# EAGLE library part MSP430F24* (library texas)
MIXED SIGNAL MICROCONTROLLER Source: http://focus.ti.com/lit/ds/symlink/msp430f2471.pdf
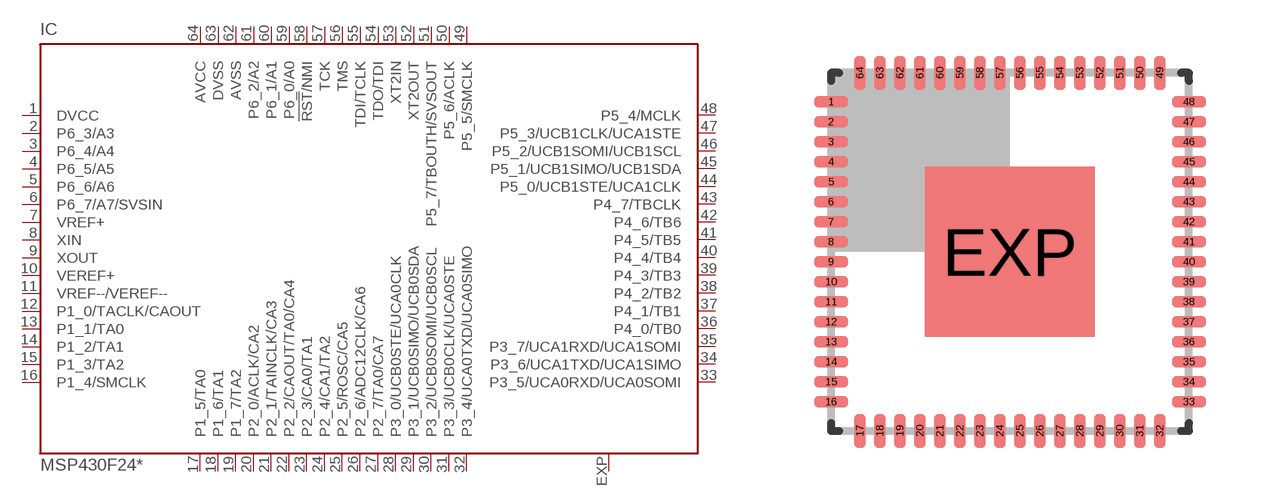
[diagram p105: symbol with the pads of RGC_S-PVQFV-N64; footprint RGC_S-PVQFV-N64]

Designator prefix IC

## MSP430F2410TRGC (MPN: MSP430F2410TRGCT; OC_FARNELL: 1649436; OC_NEWARK: 65M1704), MSP430F2447TRGC (OC_FARNELL: unknown; OC_NEWARK: unknown), MSP430F2448TRGC (OC_FARNELL: unknown; OC_NEWARK: unknown), MSP430F2449TRGC (OC_FARNELL: unknown; OC_NEWARK: unknown)  [RGC_S-PVQFV-N64]
1  DVCC  pwr
2  P6_3/A3
3  P6_4/A4
4  P6_5/A5
5  P6_6/A6
6  P6_7/A7/SVSIN
7  VREF+  out
8  XIN  in
9  XOUT  out
10  VEREF+  in
11  VREF--/VEREF--  in
12  P1_0/TACLK/CAOUT
13  P1_1/TA0
14  P1_2/TA1
15  P1_3/TA2
16  P1_4/SMCLK
17  P1_5/TA0
18  P1_6/TA1
19  P1_7/TA2
20  P2_0/ACLK/CA2
21  P2_1/TAINCLK/CA3
22  P2_2/CAOUT/TA0/CA4
23  P2_3/CA0/TA1
24  P2_4/CA1/TA2
25  P2_5/ROSC/CA5
26  P2_6/ADC12CLK/CA6
27  P2_7/TA0/CA7
28  P3_0/UCB0STE/UCA0CLK
29  P3_1/UCB0SIMO/UCB0SDA
30  P3_2/UCB0SOMI/UCB0SCL
31  P3_3/UCB0CLK/UCA0STE
32  P3_4/UCA0TXD/UCA0SIMO
33  P3_5/UCA0RXD/UCA0SOMI
34  P3_6/UCA1TXD/UCA1SIMO
35  P3_7/UCA1RXD/UCA1SOMI
36  P4_0/TB0
37  P4_1/TB1
38  P4_2/TB2
39  P4_3/TB3
40  P4_4/TB4
41  P4_5/TB5
42  P4_6/TB6
43  P4_7/TBCLK
44  P5_0/UCB1STE/UCA1CLK
45  P5_1/UCB1SIMO/UCB1SDA
46  P5_2/UCB1SOMI/UCB1SCL
47  P5_3/UCB1CLK/UCA1STE
48  P5_4/MCLK
49  P5_5/SMCLK
50  P5_6/ACLK
51  P5_7/TBOUTH/SVSOUT
52  XT2OUT  out
53  XT2IN  in
54  TDO/TDI
55  TDI/TCLK  in
56  TMS  in
57  TCK  in
58  !RST!/NMI  in
59  P6_0/A0
60  P6_1/A1
61  P6_2/A2
62  AVSS  pwr
63  DVSS  pwr
64  AVCC  pwr
EXP  EXP  pas

## Footprint RGC_S-PVQFV-N64 (pad centres in mm)
RGC(S-PVQFN-N64) CUSTOM DEVICE PASTRIC QUAD FLATPACK NO-LEAD Source: http://focus.ti.com/lit/ds/symlink/msp430f2471.pdf
smd 0.85 x 0.28: 1 -4.475,3.75; 2 -4.475,3.25; 3 -4.475,2.75; 4 -4.475,2.25; 5 -4.475,1.75; 6 -4.475,1.25; 7 -4.475,0.75; 8 -4.475,0.25; 9 -4.475,-0.25; 10 -4.475,-0.75; 11 -4.475,-1.25; 12 -4.475,-1.75; 13 -4.475,-2.25; 14 -4.475,-2.75; 15 -4.475,-3.25; 16 -4.475,-3.75; 33 4.475,-3.75; 34 4.475,-3.25; 35 4.475,-2.75; 36 4.475,-2.25; 37 4.475,-1.75; 38 4.475,-1.25; 39 4.475,-0.75; 40 4.475,-0.25; 41 4.475,0.25; 42 4.475,0.75; 43 4.475,1.25; 44 4.475,1.75; 45 4.475,2.25; 46 4.475,2.75; 47 4.475,3.25; 48 4.475,3.75
smd 0.28 x 0.85: 17 -3.75,-4.475; 18 -3.25,-4.475; 19 -2.75,-4.475; 20 -2.25,-4.475; 21 -1.75,-4.475; 22 -1.25,-4.475; 23 -0.75,-4.475; 24 -0.25,-4.475; 25 0.25,-4.475; 26 0.75,-4.475; 27 1.25,-4.475; 28 1.75,-4.475; 29 2.25,-4.475; 30 2.75,-4.475; 31 3.25,-4.475; 32 3.75,-4.475; 49 3.75,4.475; 50 3.25,4.475; 51 2.75,4.475; 52 2.25,4.475; 53 1.75,4.475; 54 1.25,4.475; 55 0.75,4.475; 56 0.25,4.475; 57 -0.25,4.475; 58 -0.75,4.475; 59 -1.25,4.475; 60 -1.75,4.475; 61 -2.25,4.475; 62 -2.75,4.475; 63 -3.25,4.475; 64 -3.75,4.475
smd 4.25 x 4.25: EXP 0,0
